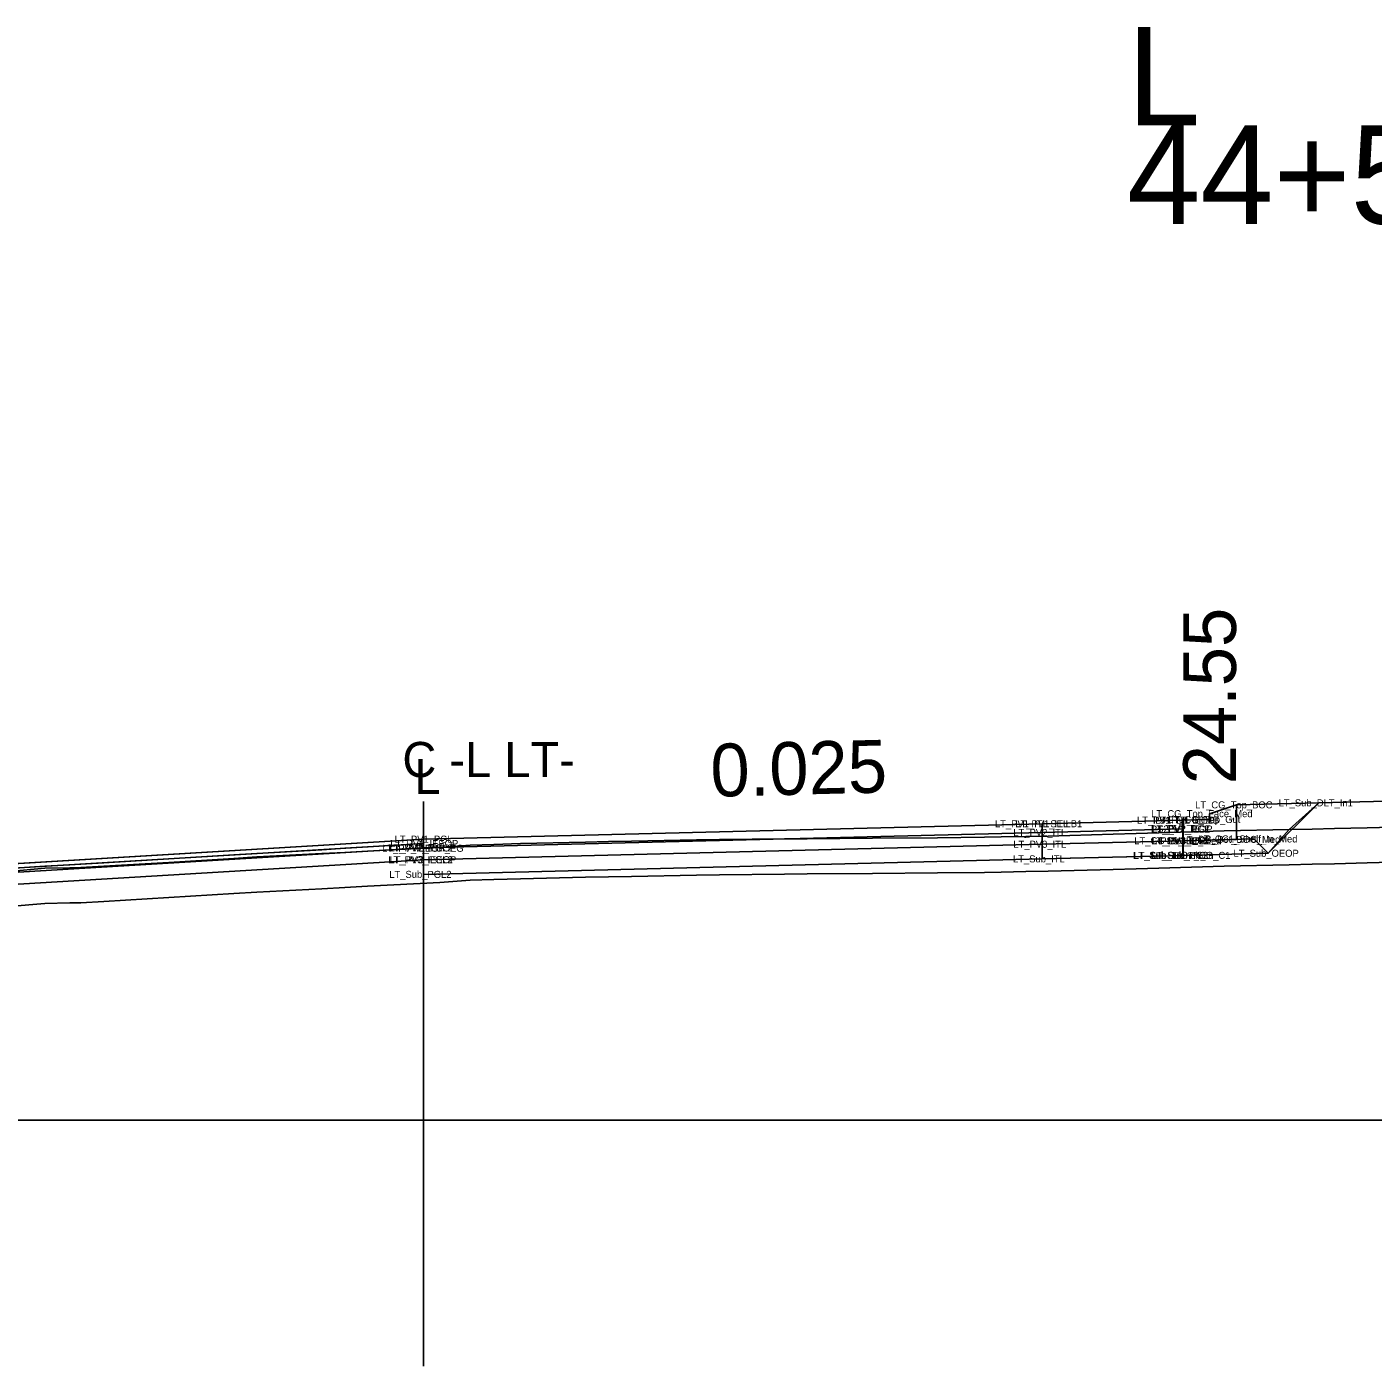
# Model space of a CAD drawing. Extents: x 2177029 to 2201446, y 59897 to 78390.
# Drawn here: x 2200201.45 to 2200239.72, y 65400.32 to 65438.39 of the extents above; entities that cross this region are included whole.
import ezdxf

# ---------------------------------------------------------------- set-up
doc = ezdxf.new("R2010")
doc.units = 0
for name, color, linetype in [('Exist CMT Pavement', 7, 'Continuous'), ('Exist Cross Section Cell', 7, 'Continuous'), ('Exist PHM Roadway Shape', 7, 'Continuous'), ('Exist XS Ground Line', 7, 'Continuous'), ('Old_Level_11', 7, 'Continuous'), ('Prop CMT Conc Surface', 7, 'Continuous'), ('Prop CMT Concrete Structures', 7, 'Continuous'), ('Prop CMT Guardrail Graphics', 7, 'Continuous'), ('Prop CMT Pvmt Course 1', 7, 'Continuous'), ('Prop CMT Pvmt Course 1 CG', 7, 'Continuous'), ('Prop CMT Pvmt Course 2', 7, 'Continuous'), ('Prop CMT Pvmt Course 2 CG', 7, 'Continuous'), ('Prop CMT Pvmt Course 3', 7, 'Continuous'), ('Prop CMT Pvmt Course 4', 7, 'Continuous'), ('Prop CMT Pvmt Surface', 7, 'Continuous'), ('Prop CMT Pvmt Wedge Surface 1', 7, 'Continuous'), ('Prop CMT Slope Grass', 7, 'Continuous'), ('Prop CMT Subgrade Earthwork', 7, 'Continuous'), ('Prop CMT Top Wall Envelope', 7, 'Continuous'), ('Prop Hatching', 7, 'Continuous'), ('Prop Horizontal Alignment', 7, 'Continuous'), ('Prop Retaining Wall', 7, 'Continuous'), ('Prop Terminator CELL', 7, 'Continuous'), ('Prop XS Side Slope Text', 7, 'Continuous'), ('Scratch_Level_0', 7, 'Continuous'), ('Scratch_Level_9', 7, 'Continuous')]:
    doc.layers.add(name, color=color, linetype=linetype)

msp = doc.modelspace()

# ---------------------------------------------------------------- linework, layer by layer
at = {"layer": 'Exist CMT Pavement'}
msp.add_line((2200212.732, 65400.32), (2200212.732, 65416.366), dxfattribs=at)
at = {"layer": 'Exist Cross Section Cell'}
msp.add_line((2200042.732, 65407.31), (2200242.732, 65407.31), dxfattribs=at)
at = {"layer": 'Exist XS Ground Line'}
msp.add_lwpolyline([(2200200.944, 65414.38), (2200201.961, 65414.473), (2200202.672, 65414.485), (2200202.989, 65414.492), (2200203.64, 65414.531), (2200205.489, 65414.638), (2200207.337, 65414.753), (2200207.989, 65414.794), (2200209.838, 65414.891), (2200210.489, 65414.924), (2200211.14, 65414.959), (2200213.193, 65415.067), (2200213.558, 65415.094), (2200214.05, 65415.129), (2200214.723, 65415.149), (2200215.489, 65415.175), (2200217.338, 65415.214), (2200217.989, 65415.228), (2200218.64, 65415.24), (2200220.489, 65415.277), (2200221.14, 65415.285), (2200222.989, 65415.307), (2200223.64, 65415.312), (2200225.489, 65415.327), (2200227.338, 65415.34), (2200228.674, 65415.353), (2200229.152, 65415.363), (2200229.855, 65415.376), (2200230.489, 65415.388), (2200232.339, 65415.439), (2200232.989, 65415.457), (2200233.638, 65415.477), (2200235.489, 65415.531), (2200237.339, 65415.573), (2200237.989, 65415.587), (2200238.628, 65415.602), (2200239.559, 65415.624), (2200240.614, 65415.651)], dxfattribs=at)
at = {"layer": 'Prop CMT Conc Surface'}
for points in [[(2200212.732, 65415.173), (2200178.215, 65413.102)], [(2200212.732, 65415.298), (2200212.732, 65415.048), (2200212.732, 65415.048), (2200212.732, 65415.173)]]:
    msp.add_lwpolyline(points, dxfattribs=at)
at = {"layer": 'Prop CMT Concrete Structures'}
for p, q in [((2200212.732, 65415.298), (2200230.318, 65415.738)), ((2200230.318, 65415.738), (2200230.317, 65415.738)), ((2200234.317, 65415.838), (2200234.325, 65415.838)), ((2200234.325, 65415.838), (2200234.327, 65415.838)), ((2200212.732, 65415.298), (2200176.732, 65413.138))]:
    msp.add_line(p, q, dxfattribs=at)
at = {"layer": 'Prop CMT Guardrail Graphics'}
for points in [[(2200212.732, 65415.298), (2200212.732, 65414.715)], [(2200212.732, 65414.715), (2200176.732, 65412.555)]]:
    msp.add_lwpolyline(points, dxfattribs=at)
at = {"layer": 'Prop CMT Pvmt Course 1'}
for points in [[(2200211.822, 65414.994), (2200212.732, 65415.048)], [(2200212.732, 65415.04), (2200211.822, 65414.994)], [(2200212.732, 65415.048), (2200212.732, 65415.04)]]:
    msp.add_lwpolyline(points, dxfattribs=at)
at = {"layer": 'Prop CMT Pvmt Course 1 CG'}
for points in [[(2200234.317, 65415.254), (2200230.317, 65415.154)], [(2200230.317, 65415.154), (2200230.317, 65414.738)], [(2200234.317, 65414.838), (2200234.317, 65415.254)], [(2200230.317, 65414.738), (2200234.317, 65414.838)]]:
    msp.add_lwpolyline(points, dxfattribs=at)
at = {"layer": 'Prop CMT Pvmt Course 2'}
for points in [[(2200212.732, 65414.715), (2200230.317, 65415.154)], [(2200230.317, 65415.154), (2200230.317, 65414.738)], [(2200234.317, 65415.254), (2200234.327, 65415.255)], [(2200234.317, 65414.838), (2200234.317, 65415.254)], [(2200234.327, 65415.255), (2200234.327, 65414.838)], [(2200230.317, 65414.738), (2200212.732, 65414.298)], [(2200212.732, 65414.298), (2200212.732, 65414.715)], [(2200234.327, 65414.838), (2200234.317, 65414.838)]]:
    msp.add_lwpolyline(points, dxfattribs=at)
at = {"layer": 'Prop CMT Pvmt Course 2 CG'}
for points in [[(2200212.732, 65415.298), (2200230.317, 65415.738)], [(2200230.317, 65415.488), (2200212.732, 65415.048)], [(2200230.317, 65415.738), (2200230.317, 65415.488)], [(2200234.317, 65415.838), (2200234.327, 65415.838)], [(2200234.317, 65415.588), (2200234.317, 65415.838)], [(2200234.327, 65415.588), (2200234.317, 65415.588)], [(2200234.327, 65415.838), (2200234.327, 65415.588)], [(2200212.732, 65415.298), (2200176.732, 65413.138)], [(2200178.215, 65413.102), (2200212.732, 65415.173)], [(2200212.732, 65415.048), (2200212.732, 65415.298)], [(2200212.732, 65415.048), (2200212.732, 65415.298)], [(2200212.732, 65415.173), (2200212.732, 65415.048), (2200212.732, 65415.048)]]:
    msp.add_lwpolyline(points, dxfattribs=at)
at = {"layer": 'Prop CMT Pvmt Course 3'}
msp.add_line((2200212.732, 65415.043), (2200212.732, 65414.298), dxfattribs=at)
for points in [[(2200238.178, 65416.332), (2200236.743, 65414.898)], [(2200212.732, 65414.298), (2200230.317, 65414.738)], [(2200230.317, 65414.738), (2200234.317, 65414.838)], [(2200234.317, 65414.838), (2200234.327, 65414.838)], [(2200234.327, 65414.838), (2200236.743, 65414.898)], [(2200234.327, 65414.838), (2200234.327, 65414.838)]]:
    msp.add_lwpolyline(points, dxfattribs=at)
at = {"layer": 'Prop CMT Pvmt Course 4'}
msp.add_lwpolyline([(2200230.317, 65415.738), (2200234.317, 65415.838)], dxfattribs=at)
at = {"layer": 'Prop CMT Pvmt Surface'}
for points in [[(2200200.944, 65414.466), (2200201.961, 65414.527), (2200202.672, 65414.57), (2200202.989, 65414.589), (2200203.64, 65414.628), (2200205.489, 65414.739), (2200207.337, 65414.85), (2200207.989, 65414.889), (2200209.838, 65415), (2200210.489, 65415.039), (2200211.14, 65415.078), (2200212.732, 65415.173)], [(2200212.732, 65415.173), (2200212.732, 65415.048)], [(2200212.732, 65415.048), (2200211.822, 65414.994), (2200211.14, 65414.959), (2200210.489, 65414.924), (2200209.838, 65414.891), (2200207.989, 65414.794), (2200207.337, 65414.753), (2200205.489, 65414.638), (2200203.64, 65414.531), (2200202.989, 65414.492), (2200202.672, 65414.485), (2200201.961, 65414.473), (2200200.944, 65414.38)]]:
    msp.add_lwpolyline(points, dxfattribs=at)
at = {"layer": 'Prop CMT Pvmt Wedge Surface 1'}
for p, q in [((2200223.64, 65414.312), (2200225.489, 65414.327)), ((2200225.489, 65414.327), (2200227.338, 65414.34)), ((2200227.338, 65414.34), (2200228.674, 65414.353)), ((2200228.674, 65414.353), (2200229.152, 65414.363)), ((2200229.152, 65414.363), (2200229.855, 65414.376)), ((2200229.855, 65414.376), (2200230.489, 65414.388)), ((2200230.489, 65414.388), (2200232.339, 65414.439)), ((2200232.339, 65414.439), (2200232.989, 65414.457)), ((2200232.989, 65414.457), (2200233.638, 65414.477)), ((2200233.638, 65414.477), (2200235.489, 65414.531)), ((2200235.489, 65414.531), (2200237.339, 65414.573)), ((2200237.339, 65414.573), (2200237.989, 65414.587)), ((2200237.989, 65414.587), (2200238.628, 65414.602)), ((2200238.628, 65414.602), (2200239.559, 65414.624)), ((2200239.559, 65414.624), (2200240.614, 65414.651)), ((2200210.489, 65413.924), (2200211.14, 65413.959)), ((2200211.14, 65413.959), (2200213.193, 65414.067)), ((2200213.193, 65414.067), (2200213.558, 65414.094)), ((2200213.558, 65414.094), (2200214.05, 65414.129)), ((2200214.05, 65414.129), (2200214.723, 65414.149)), ((2200214.723, 65414.149), (2200215.489, 65414.175)), ((2200215.489, 65414.175), (2200217.338, 65414.214)), ((2200217.338, 65414.214), (2200217.989, 65414.228)), ((2200217.989, 65414.228), (2200218.64, 65414.24)), ((2200218.64, 65414.24), (2200220.489, 65414.277)), ((2200220.489, 65414.277), (2200221.14, 65414.285)), ((2200221.14, 65414.285), (2200222.989, 65414.307)), ((2200222.989, 65414.307), (2200223.64, 65414.312)), ((2200203.64, 65413.531), (2200205.489, 65413.638)), ((2200205.489, 65413.638), (2200207.337, 65413.753)), ((2200207.337, 65413.753), (2200207.989, 65413.794)), ((2200207.989, 65413.794), (2200209.838, 65413.891)), ((2200209.838, 65413.891), (2200210.489, 65413.924)), ((2200200.944, 65413.38), (2200201.961, 65413.473)), ((2200201.961, 65413.473), (2200202.672, 65413.485)), ((2200202.672, 65413.485), (2200202.989, 65413.492)), ((2200202.989, 65413.492), (2200203.64, 65413.531))]:
    msp.add_line(p, q, dxfattribs=at)
at = {"layer": 'Prop CMT Slope Grass'}
for points in [[(2200212.732, 65415.048), (2200230.317, 65415.488)], [(2200230.317, 65415.488), (2200230.317, 65415.154)], [(2200234.317, 65415.254), (2200234.317, 65415.588)], [(2200234.317, 65415.588), (2200234.327, 65415.588)], [(2200234.327, 65415.588), (2200234.327, 65415.255)], [(2200230.317, 65415.154), (2200212.732, 65414.715)], [(2200234.327, 65415.255), (2200234.317, 65415.254)], [(2200212.732, 65414.715), (2200212.732, 65415.048)]]:
    msp.add_lwpolyline(points, dxfattribs=at)
at = {"layer": 'Prop CMT Subgrade Earthwork'}
for points in [[(2200212.732, 65415.298), (2200212.732, 65415.048)], [(2200212.732, 65415.048), (2200176.732, 65412.888)]]:
    msp.add_lwpolyline(points, dxfattribs=at)
at = {"layer": 'Prop Hatching'}
msp.add_lwpolyline([(2200235.837, 65416.273), (2200241.304, 65416.411)], dxfattribs=at)
at = {"layer": 'Prop Horizontal Alignment'}
for points in [[(2200234.327, 65415.255), (2200236.337, 65415.305), (2200236.743, 65414.898)], [(2200234.327, 65414.838), (2200234.327, 65415.255)], [(2200236.743, 65414.898), (2200234.327, 65414.838)]]:
    msp.add_lwpolyline(points, dxfattribs=at)
at = {"layer": 'Prop Retaining Wall'}
msp.add_lwpolyline([(2200234.327, 65415.838), (2200235.077, 65415.857), (2200235.078, 65416.023), (2200235.837, 65416.273)], dxfattribs=at)
at = {"layer": 'Prop Terminator CELL'}
for points in [[(2200234.327, 65415.838), (2200235.077, 65415.857), (2200235.078, 65416.023), (2200235.837, 65416.273)], [(2200235.837, 65416.273), (2200235.837, 65415.292)], [(2200234.327, 65415.255), (2200234.327, 65415.838)], [(2200235.837, 65415.292), (2200234.327, 65415.255)]]:
    msp.add_lwpolyline(points, dxfattribs=at)
at = {"layer": 'Prop XS Side Slope Text'}
msp.add_lwpolyline([(2200176.722, 65413.137), (2200212.732, 65415.298), (2200230.317, 65415.738), (2200234.317, 65415.838), (2200235.077, 65415.857), (2200235.078, 65416.023), (2200235.837, 65416.273), (2200238.178, 65416.332), (2200237.339, 65415.573), (2200235.489, 65415.531), (2200233.638, 65415.477), (2200232.989, 65415.457), (2200232.339, 65415.439), (2200230.489, 65415.388), (2200229.855, 65415.376), (2200229.152, 65415.363), (2200228.674, 65415.353), (2200227.338, 65415.34), (2200225.489, 65415.327), (2200223.64, 65415.312), (2200222.989, 65415.307), (2200221.14, 65415.285), (2200220.489, 65415.277), (2200218.64, 65415.24), (2200217.989, 65415.228), (2200217.338, 65415.214), (2200215.489, 65415.175), (2200214.723, 65415.149), (2200214.05, 65415.129), (2200213.558, 65415.094), (2200213.193, 65415.067), (2200212.732, 65415.043), (2200211.14, 65414.959), (2200210.489, 65414.924), (2200209.838, 65414.891), (2200207.989, 65414.794), (2200207.337, 65414.753), (2200205.489, 65414.638), (2200203.64, 65414.531), (2200202.989, 65414.492), (2200202.672, 65414.485), (2200201.961, 65414.473), (2200200.944, 65414.38)], dxfattribs=at)
for points in [[(2200238.178, 65416.332), (2200241.304, 65416.411), (2200242.732, 65416.079), (2200242.732, 65415.475), (2200241.328, 65415.672), (2200240.614, 65415.651), (2200239.559, 65415.624), (2200238.628, 65415.602), (2200237.989, 65415.587), (2200237.339, 65415.573)], [(2200234.327, 65414.838), (2200236.743, 65414.898), (2200237.339, 65415.573), (2200235.489, 65415.531), (2200233.638, 65415.477), (2200232.989, 65415.457), (2200232.339, 65415.439), (2200230.489, 65415.388), (2200229.855, 65415.376), (2200229.152, 65415.363), (2200228.674, 65415.353), (2200227.338, 65415.34), (2200225.489, 65415.327), (2200223.64, 65415.312), (2200222.989, 65415.307), (2200221.14, 65415.285), (2200220.489, 65415.277), (2200218.64, 65415.24), (2200217.989, 65415.228), (2200217.338, 65415.214), (2200215.489, 65415.175), (2200214.723, 65415.149), (2200214.05, 65415.129), (2200213.558, 65415.094), (2200213.193, 65415.067), (2200212.732, 65415.043), (2200212.732, 65414.298), (2200230.317, 65414.738)]]:
    msp.add_lwpolyline(points, close=True, dxfattribs=at)
at = {"layer": 'Scratch_Level_0'}
for points in [[(2200230.317, 65415.488), (2200234.317, 65415.588)], [(2200230.317, 65415.154), (2200230.317, 65415.488)], [(2200234.317, 65415.588), (2200234.317, 65415.254)], [(2200234.317, 65415.254), (2200230.317, 65415.154)]]:
    msp.add_lwpolyline(points, dxfattribs=at)
at = {"layer": 'Scratch_Level_9'}
for points in [[(2200230.317, 65415.738), (2200234.317, 65415.838)], [(2200230.317, 65415.488), (2200230.317, 65415.738)], [(2200234.317, 65415.588), (2200230.317, 65415.488)], [(2200234.317, 65415.838), (2200234.317, 65415.588)]]:
    msp.add_lwpolyline(points, dxfattribs=at)

# ---------------------------------------------------------------- texts
at = {"layer": 'Exist CMT Pavement'}
for s, p in [('C -L LT-', (2200212.127, 65417.062)), ('L', (2200212.47, 65416.581))]:
    msp.add_text(s, height=1, dxfattribs=at).set_placement(p)
at = {"layer": 'Exist Cross Section Cell'}
for s, p in [('L', (2200232.732, 65435.588)), ('44+50.00 / 1', (2200232.732, 65432.788))]:
    msp.add_text(s, height=2.8, dxfattribs=at).set_placement(p)
at = {"layer": 'Exist PHM Roadway Shape'}
for s, p in [('LT_CG_Top_BOC', (2200234.665, 65416.173)), ('LT_Sub_DLT_In1', (2200237.039, 65416.232)), ('LT_PV1_ITL SE LB', (2200233.013, 65415.738)), ('LT_CG_Top_Face_Med', (2200233.415, 65415.923)), ('PS1_LT_IEOP', (2200233.462, 65415.738)), ('LT_PV1_ITL1', (2200233.531, 65415.738)), ('LT_CG_Top_Gut', (2200233.901, 65415.757)), ('LT_PV1_ITL SE LB1', (2200228.974, 65415.638)), ('LT_PV2_ITL', (2200229.497, 65415.388)), ('LT_PV1_ITL', (2200229.553, 65415.638)), ('PS2_LT_IEOP', (2200233.406, 65415.488)), ('LT_PV2_ITL2', (2200233.417, 65415.488)), ('LT_PV2_PGL', (2200233.439, 65415.488)), ('LT_PV_IEEOP_EG', (2200211.55, 65414.94)), ('LT_PV2_IEEOP', (2200211.727, 65414.948)), ('LT_PV2_PGL2', (2200211.763, 65414.948)), ('LT_PV1_IEEOP', (2200211.784, 65415.073)), ('LT_PV1_PGL', (2200211.909, 65415.198)), ('LT_PV3_ITL', (2200229.497, 65415.054)), ('LT_CG_Bot_IE_Med', (2200232.934, 65415.155)), ('LT_PV3_ITL2', (2200233.417, 65415.155)), ('LT_PV3_PGL', (2200233.439, 65415.154)), ('PS3_IEOP', (2200233.675, 65415.154)), ('LT_CG_Bot_BOC_Med', (2200234.279, 65415.192)), ('LT_CG1_Shelf_In_Med', (2200234.765, 65415.205)), ('LT_PV3_IEEOP', (2200211.727, 65414.615)), ('LT_PV3_PGL2', (2200211.763, 65414.615)), ('LT_Sub_ITL', (2200229.487, 65414.638)), ('LT_Sub_Trench_In', (2200232.9, 65414.738)), ('LT_Sub_IEOT_CG_C1', (2200232.919, 65414.738)), ('LT_Sub_ITL2', (2200233.408, 65414.738)), ('LT_Sub_PGL', (2200233.429, 65414.738)), ('LT_Sub_OEOP', (2200235.754, 65414.798)), ('LT_Sub_PGL2', (2200211.754, 65414.198))]:
    msp.add_text(s, height=0.2, dxfattribs=at).set_placement(p)
at = {"layer": 'Old_Level_11'}
msp.add_text('0.025', height=1.5, rotation=1.4324, dxfattribs=at).set_placement((2200220.904, 65416.503))
at = {"layer": 'Prop CMT Top Wall Envelope'}
msp.add_text('24.55', height=1.5, rotation=90, dxfattribs=at).set_placement((2200235.827, 65416.857))

doc.saveas('drawing.dxf')
